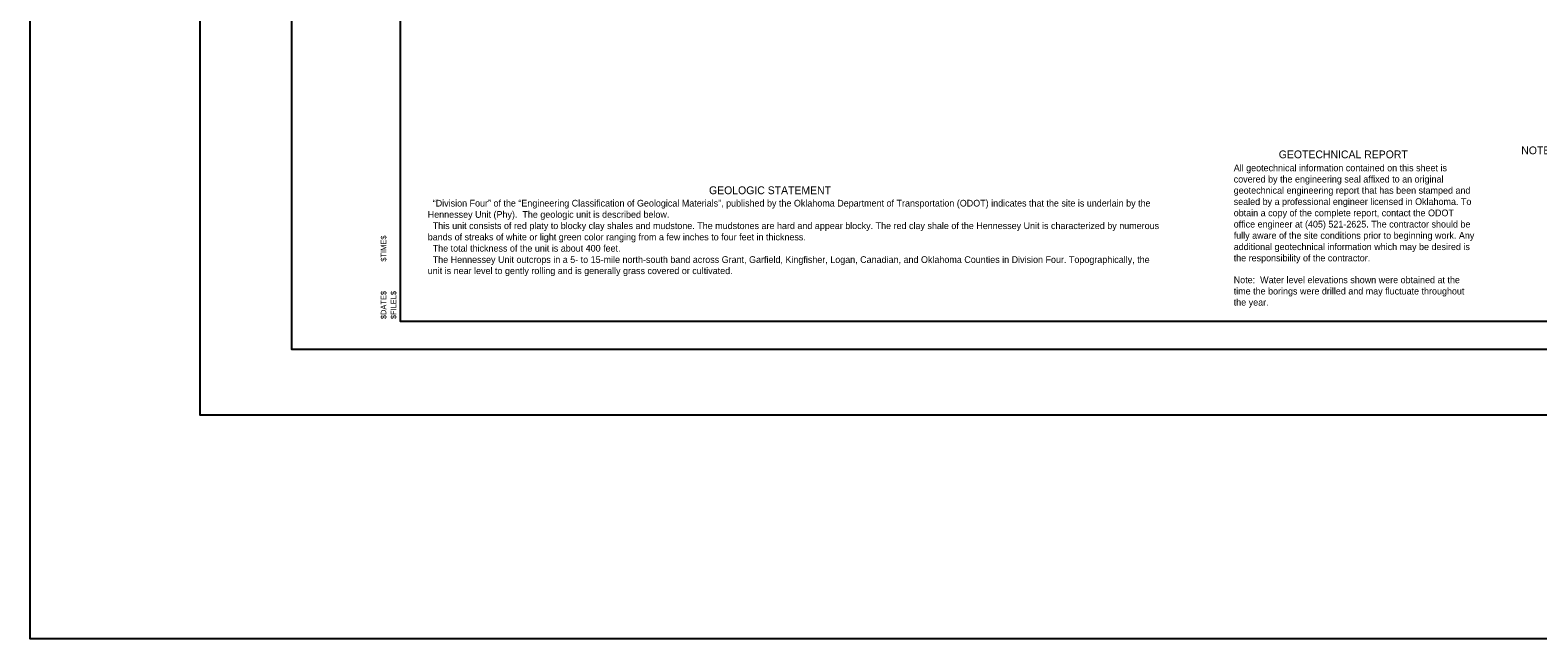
# Model space of a CAD drawing. Extents: x 2150161.5 to 2150203.1, y 143779.5 to 143868.5.
# Drawn here: x 2150161.53 to 2150188.52, y 143779.54 to 143790.44 of the extents above; entities that cross this region are included whole.
import ezdxf

# ---------------------------------------------------------------- set-up
doc = ezdxf.new("R2010")
doc.units = 0
for name, color, linetype in [('S', 7, 'Continuous'), ('SHT_Plot_Shape_Full', 7, 'Continuous'), ('SHT_Plot_Shape_Half', 7, 'Continuous'), ('SHT_Plot_Stamp', 7, 'Continuous'), ('SHT_Sheet_Border', 7, 'Continuous'), ('Text', 7, 'Continuous')]:
    doc.layers.add(name, color=color, linetype=linetype)

# ---------------------------------------------------------------- blocks, each defined once
blk = doc.blocks.new('Stamp_Plot_Stamp')
at = {"layer": 'SHT_Plot_Stamp'}
for s, p in [('$TIME$', (1.695, 1.572)), ('$DATE$', (1.695, 0.542)), ('$FILEL$', (1.873, 0.542))]:
    blk.add_text(s, height=0.1, rotation=90, dxfattribs=at).set_placement(p)

msp = doc.modelspace()

# ---------------------------------------------------------------- linework, layer by layer
at = {"layer": 'S'}
msp.add_lwpolyline([(2150161.53, 143868.477), (2150203.071, 143868.477), (2150203.071, 143779.536), (2150161.53, 143779.536)], close=True, dxfattribs=at)
at = {"layer": 'SHT_Plot_Shape_Full'}
msp.add_lwpolyline([(2150164.575, 143807.544), (2150200.575, 143807.544), (2150200.575, 143783.544), (2150164.575, 143783.544)], close=True, dxfattribs=at)
at = {"layer": 'SHT_Plot_Shape_Half'}
msp.add_lwpolyline([(2150166.212, 143806.719), (2150200.212, 143806.719), (2150200.212, 143784.719), (2150166.212, 143784.719)], close=True, dxfattribs=at)
at = {"layer": 'SHT_Sheet_Border'}
msp.add_lwpolyline([(2150199.662, 143785.219), (2150168.162, 143785.219), (2150168.162, 143806.219), (2150199.662, 143806.219)], close=True, dxfattribs=at)

# ---------------------------------------------------------------- block references
at = {"layer": 'SHT_Plot_Stamp'}
msp.add_blockref('Stamp_Plot_Stamp', (2150166.212, 143784.719), dxfattribs=at)

# ---------------------------------------------------------------- texts
at = {"layer": 'Text'}
for s, height, p in [('GEOTECHNICAL REPORT', 0.14, (2150183.885, 143788.142)), ('NOTE:', 0.14, (2150188.226, 143788.214)), ('All geotechnical information contained on this sheet is ', 0.12, (2150183.078, 143787.91)), ('covered by the engineering seal affixed to an original ', 0.12, (2150183.078, 143787.708)), ('GEOLOGIC STATEMENT', 0.14, (2150173.684, 143787.499)), ('geotechnical engineering report that has been stamped and ', 0.12, (2150183.078, 143787.508)), ('Hennessey Unit (Phy).  The geologic unit is described below. ', 0.12, (2150168.648, 143787.076)), ('  “Division Four” of the “Engineering Classification of Geological Materials”, published by the Oklahoma Department of Transportation (ODOT) indicates that the site is underlain by the ', 0.12, (2150168.648, 143787.278)), ('sealed by a professional engineer licensed in Oklahoma. To ', 0.12, (2150183.078, 143787.306)), ('obtain a copy of the complete report, contact the ODOT ', 0.12, (2150183.078, 143787.104)), ('  This unit consists of red platy to blocky clay shales and mudstone. The mudstones are hard and appear blocky. The red clay shale of the Hennessey Unit is characterized by numerous ', 0.12, (2150168.648, 143786.874)), ('office engineer at (405) 521-2625. The contractor should be ', 0.12, (2150183.078, 143786.902)), ('bands of streaks of white or light green color ranging from a few inches to four feet in thickness. ', 0.12, (2150168.648, 143786.672)), ('fully aware of the site conditions prior to beginning work. Any ', 0.12, (2150183.078, 143786.7)), ('  The total thickness of the unit is about 400 feet.', 0.12, (2150168.648, 143786.47)), ('  The Hennessey Unit outcrops in a 5- to 15-mile north-south band across Grant, Garfield, Kingfisher, Logan, Canadian, and Oklahoma Counties in Division Four. Topographically, the ', 0.12, (2150168.648, 143786.268)), ('the responsibility of the contractor.', 0.12, (2150183.078, 143786.296)), ('additional geotechnical information which may be desired is ', 0.12, (2150183.078, 143786.498)), ('unit is near level to gently rolling and is generally grass covered or cultivated.', 0.12, (2150168.648, 143786.068)), ('time the borings were drilled and may fluctuate throughout ', 0.12, (2150183.078, 143785.703)), ('Note:  Water level elevations shown were obtained at the ', 0.12, (2150183.078, 143785.905)), ('the year.', 0.12, (2150183.078, 143785.503))]:
    msp.add_text(s, height=height, dxfattribs=at).set_placement(p)

doc.saveas('drawing.dxf')
